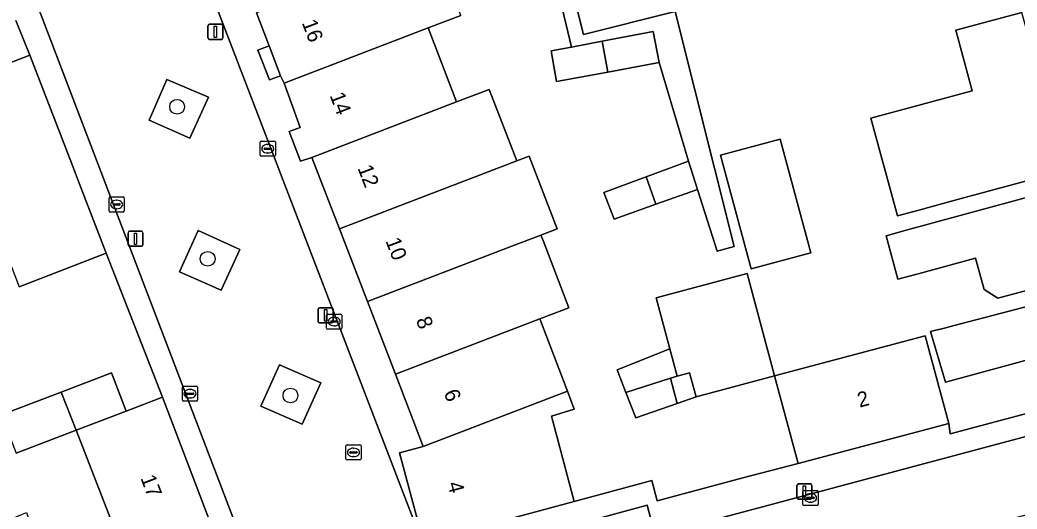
# Model space of a CAD drawing. Extents: x 159262 to 160143, y 383399 to 384319.
# Drawn here: x 159589.7 to 159655.5, y 383642.1 to 383674.4 of the extents above; entities that cross this region are included whole.
import ezdxf

# ---------------------------------------------------------------- set-up
doc = ezdxf.new("R2010")
doc.units = 0
for name, color, linetype in [('IMGEO_Boom', 7, 'Continuous'), ('IMGEO_Erf', 7, 'Continuous'), ('IMGEO_Groenvoorziening', 7, 'Continuous'), ('IMGEO_Hek', 7, 'Continuous'), ('IMGEO_Kolk', 7, 'Continuous'), ('IMGEO_Lichtmast', 7, 'Continuous'), ('IMGEO_Muur', 7, 'Continuous'), ('IMGEO_Pand', 7, 'Continuous'), ('IMGEO_Pand_nummerreeks', 7, 'Continuous'), ('IMGEO_Pand_overbouw', 7, 'Continuous'), ('IMGEO_Parkeervlak_open', 7, 'Continuous'), ('IMGEO_Rijbaan_lokaal_open', 7, 'Continuous'), ('IMGEO_Rioolput', 7, 'Continuous'), ('IMGEO_Voetpad_open', 7, 'Continuous')]:
    doc.layers.add(name, color=color, linetype=linetype)

msp = doc.modelspace()

# ---------------------------------------------------------------- linework, layer by layer
at = {"layer": 'IMGEO_Boom'}
for centre in [(159600.06, 383668.66), (159602.083, 383658.612), (159607.547, 383649.577)]:
    msp.add_circle(centre, 0.489, dxfattribs=at)
at = {"layer": 'IMGEO_Erf'}
for points in [[(159623.97, 383685.078), (159626.897, 383673.438), (159632.943, 383674.959), (159636.849, 383659.425), (159635.725, 383659.121), (159634.434, 383663.202), (159631.679, 383662.222), (159628.924, 383661.241), (159628.242, 383662.985), (159631.042, 383664.028), (159633.843, 383665.07), (159631.887, 383671.579), (159628.507, 383670.955), (159625.126, 383670.331), (159624.753, 383672.355), (159626.096, 383672.609), (159624.084, 383681.116)], [(159618.792, 383674.698), (159616.644, 383673.873), (159618.515, 383668.985), (159620.674, 383669.814), (159622.496, 383665.086), (159623.314, 383665.4), (159625.156, 383660.591), (159624.086, 383660.18), (159624.226, 383659.814), (159625.927, 383655.371), (159624.01, 383654.635), (159625.837, 383649.864), (159626.292, 383648.676), (159624.78, 383648.209), (159626.292, 383642.574), (159631.419, 383643.955), (159631.774, 383642.614), (159637.425, 383644.126), (159641.074, 383645.085), (159639.518, 383650.871), (159649.459, 383653.522), (159651.016, 383647.728), (159651.108, 383647.049), (159659.22, 383649.202)], [(159658.698, 383664.453), (159651.845, 383662.591), (159649.042, 383661.829), (159647.632, 383661.446), (159645.877, 383667.903), (159652.559, 383669.711), (159651.485, 383673.719), (159655.851, 383674.889)], [(159587.478, 383670.969), (159590.343, 383672.068), (159589.409, 383674.359)], [(159656.899, 383656.72), (159654.264, 383656.004), (159653.354, 383656.585), (159652.792, 383658.652), (159648.995, 383657.62), (159647.664, 383657.258), (159646.882, 383660.14), (159648.213, 383660.502), (159655.345, 383662.44), (159658.977, 383663.427)], [(159588.464, 383648.295), (159592.408, 383649.797), (159595.736, 383651.065), (159596.696, 383648.546), (159599.106, 383649.464), (159595.372, 383658.975), (159589.631, 383656.769)], [(159658.329, 383652.508), (159652.342, 383650.882), (159651.146, 383650.557), (159650.797, 383650.462), (159649.823, 383653.797), (159650.173, 383653.888), (159650.64, 383654.01), (159651.373, 383654.201), (159657.446, 383655.786)], [(159588.581, 383641.206), (159590.125, 383641.835), (159591.119, 383638.714), (159596.105, 383640.302), (159593.386, 383647.285), (159589.424, 383645.776)]]:
    msp.add_lwpolyline(points, dxfattribs=at)
for points in [[(159639.884, 383666.526), (159641.913, 383659.014), (159637.98, 383657.951), (159635.951, 383665.464)], [(159639.518, 383650.871), (159634.331, 383649.487), (159633.082, 383649.053), (159630.344, 383648.101), (159629.703, 383649.773), (159629.128, 383651.276), (159632.598, 383652.671), (159631.702, 383656.03), (159637.714, 383657.634)]]:
    msp.add_lwpolyline(points, close=True, dxfattribs=at)
at = {"layer": 'IMGEO_Groenvoorziening'}
for points in [[(159600.904, 383666.584), (159602.138, 383669.297), (159599.377, 383670.47), (159598.214, 383667.773)], [(159602.97, 383656.544), (159604.194, 383659.235), (159601.453, 383660.478), (159600.227, 383657.755)], [(159608.329, 383647.691), (159609.547, 383650.425), (159606.824, 383651.602), (159605.592, 383648.88)]]:
    msp.add_lwpolyline(points, close=True, dxfattribs=at)
at = {"layer": 'IMGEO_Hek'}
msp.add_lwpolyline([(159631.774, 383642.614), (159637.425, 383644.126)], dxfattribs=at)
at = {"layer": 'IMGEO_Kolk'}
for p, q in [((159605.547, 383665.465), (159605.547, 383666.317)), ((159605.622, 383666.391), (159606.474, 383666.391)), ((159605.849, 383665.934), (159606.247, 383665.934)), ((159606.035, 383666.171), (159606.06, 383666.171)), ((159606.548, 383666.317), (159606.548, 383665.465)), ((159606.474, 383665.391), (159605.622, 383665.391)), ((159605.806, 383665.885), (159605.806, 383665.897)), ((159606.244, 383665.848), (159605.846, 383665.848)), ((159606.058, 383665.611), (159606.033, 383665.611)), ((159606.29, 383665.897), (159606.29, 383665.885)), ((159595.566, 383661.779), (159595.566, 383662.631)), ((159595.641, 383662.705), (159596.493, 383662.705)), ((159596.567, 383662.631), (159596.567, 383661.779)), ((159595.825, 383662.199), (159595.825, 383662.211)), ((159596.263, 383662.162), (159595.865, 383662.162)), ((159595.868, 383662.248), (159596.266, 383662.248)), ((159596.054, 383662.485), (159596.079, 383662.485)), ((159596.309, 383662.211), (159596.309, 383662.199)), ((159596.493, 383661.705), (159595.641, 383661.705)), ((159596.077, 383661.925), (159596.052, 383661.925)), ((159609.935, 383654.037), (159609.935, 383654.889)), ((159610.01, 383654.963), (159610.862, 383654.963)), ((159610.423, 383654.743), (159610.448, 383654.743)), ((159610.936, 383654.889), (159610.936, 383654.037)), ((159610.194, 383654.457), (159610.194, 383654.469)), ((159610.632, 383654.42), (159610.234, 383654.42)), ((159610.237, 383654.506), (159610.635, 383654.506)), ((159610.446, 383654.183), (159610.421, 383654.183)), ((159610.678, 383654.469), (159610.678, 383654.457)), ((159610.862, 383653.963), (159610.01, 383653.963)), ((159600.415, 383649.268), (159600.415, 383650.12)), ((159600.49, 383650.194), (159601.342, 383650.194)), ((159601.416, 383650.12), (159601.416, 383649.268)), ((159600.674, 383649.688), (159600.674, 383649.7)), ((159601.112, 383649.651), (159600.714, 383649.651)), ((159600.717, 383649.737), (159601.115, 383649.737)), ((159600.903, 383649.974), (159600.928, 383649.974)), ((159601.158, 383649.7), (159601.158, 383649.688)), ((159601.342, 383649.194), (159600.49, 383649.194)), ((159600.926, 383649.414), (159600.901, 383649.414)), ((159641.392, 383642.378), (159641.392, 383643.23)), ((159641.467, 383643.304), (159642.319, 383643.304)), ((159641.88, 383643.084), (159641.905, 383643.084)), ((159642.393, 383643.23), (159642.393, 383642.378)), ((159642.319, 383642.304), (159641.467, 383642.304)), ((159641.651, 383642.798), (159641.651, 383642.81)), ((159642.089, 383642.761), (159641.691, 383642.761)), ((159641.694, 383642.847), (159642.092, 383642.847)), ((159641.903, 383642.524), (159641.878, 383642.524)), ((159642.135, 383642.81), (159642.135, 383642.798))]:
    msp.add_line(p, q, dxfattribs=at)
for points in [[(159605.547, 383665.465), (159605.547, 383666.317)], [(159605.622, 383666.391), (159606.474, 383666.391)], [(159606.548, 383666.317), (159606.548, 383665.465)], [(159606.474, 383665.391), (159605.622, 383665.391)], [(159595.566, 383661.779), (159595.566, 383662.631)], [(159595.641, 383662.705), (159596.493, 383662.705)], [(159596.567, 383662.631), (159596.567, 383661.779)], [(159596.493, 383661.705), (159595.641, 383661.705)], [(159609.935, 383654.037), (159609.935, 383654.889)], [(159610.01, 383654.963), (159610.862, 383654.963)], [(159610.936, 383654.889), (159610.936, 383654.037)], [(159610.862, 383653.963), (159610.01, 383653.963)], [(159600.415, 383649.268), (159600.415, 383650.12)], [(159600.49, 383650.194), (159601.342, 383650.194)], [(159601.416, 383650.12), (159601.416, 383649.268)], [(159601.342, 383649.194), (159600.49, 383649.194)], [(159641.392, 383642.378), (159641.392, 383643.23)], [(159641.467, 383643.304), (159642.319, 383643.304)], [(159642.393, 383643.23), (159642.393, 383642.378)], [(159642.319, 383642.304), (159641.467, 383642.304)]]:
    msp.add_lwpolyline(points, dxfattribs=at)
for centre, radius, start, end in [((159605.624, 383666.315), 0.0765, 91.55205, 178.44795), ((159605.624, 383666.315), 0.0765, 91.55205, 178.44795), ((159605.846, 383665.894), 0.0403, 85.87752, 175.75265), ((159606.251, 383665.896), 0.0386, 1.73085, 96.63898), ((159606.472, 383666.315), 0.0765, 1.55205, 88.44795), ((159606.472, 383666.315), 0.0765, 1.55205, 88.44795), ((159605.624, 383665.467), 0.0765, 181.55205, 268.44795), ((159605.624, 383665.467), 0.0765, 181.55205, 268.44795), ((159605.843, 383665.884), 0.0366, 178.93798, 274.71019), ((159606.247, 383665.891), 0.043, 264.86636, 352.45326), ((159606.472, 383665.467), 0.0765, 271.55205, 358.44795), ((159606.472, 383665.467), 0.0765, 271.55205, 358.44795), ((159595.643, 383662.629), 0.0765, 91.55205, 178.44795), ((159595.643, 383662.629), 0.0765, 91.55205, 178.44795), ((159596.491, 383662.629), 0.0765, 1.55205, 88.44795), ((159596.491, 383662.629), 0.0765, 1.55205, 88.44795), ((159595.865, 383662.208), 0.0403, 85.87752, 175.75265), ((159595.862, 383662.198), 0.0366, 178.93798, 274.71019), ((159596.266, 383662.205), 0.043, 264.86636, 352.45326), ((159596.27, 383662.21), 0.0386, 1.73085, 96.63898), ((159595.643, 383661.781), 0.0765, 181.55205, 268.44795), ((159595.643, 383661.781), 0.0765, 181.55205, 268.44795), ((159596.491, 383661.781), 0.0765, 271.55205, 358.44795), ((159596.491, 383661.781), 0.0765, 271.55205, 358.44795), ((159610.012, 383654.887), 0.0765, 91.55205, 178.44795), ((159610.012, 383654.887), 0.0765, 91.55205, 178.44795), ((159610.86, 383654.887), 0.0765, 1.55205, 88.44795), ((159610.86, 383654.887), 0.0765, 1.55205, 88.44795), ((159610.234, 383654.466), 0.0403, 85.87752, 175.75265), ((159610.231, 383654.456), 0.0366, 178.93798, 274.71019), ((159610.635, 383654.463), 0.043, 264.86636, 352.45326), ((159610.639, 383654.468), 0.0386, 1.73085, 96.63898), ((159610.012, 383654.039), 0.0765, 181.55205, 268.44795), ((159610.012, 383654.039), 0.0765, 181.55205, 268.44795), ((159610.86, 383654.039), 0.0765, 271.55205, 358.44795), ((159610.86, 383654.039), 0.0765, 271.55205, 358.44795), ((159600.492, 383650.118), 0.0765, 91.55205, 178.44795), ((159600.492, 383650.118), 0.0765, 91.55205, 178.44795), ((159601.34, 383650.118), 0.0765, 1.55205, 88.44795), ((159601.34, 383650.118), 0.0765, 1.55205, 88.44795), ((159600.714, 383649.697), 0.0403, 85.87752, 175.75265), ((159600.711, 383649.687), 0.0366, 178.93798, 274.71019), ((159601.115, 383649.694), 0.043, 264.86636, 352.45326), ((159601.119, 383649.699), 0.0386, 1.73085, 96.63898), ((159600.492, 383649.27), 0.0765, 181.55205, 268.44795), ((159600.492, 383649.27), 0.0765, 181.55205, 268.44795), ((159601.34, 383649.27), 0.0765, 271.55205, 358.44795), ((159601.34, 383649.27), 0.0765, 271.55205, 358.44795), ((159641.469, 383643.228), 0.0765, 91.55205, 178.44795), ((159641.469, 383643.228), 0.0765, 91.55205, 178.44795), ((159642.317, 383643.228), 0.0765, 1.55205, 88.44795), ((159642.317, 383643.228), 0.0765, 1.55205, 88.44795), ((159641.469, 383642.38), 0.0765, 181.55205, 268.44795), ((159641.469, 383642.38), 0.0765, 181.55205, 268.44795), ((159641.691, 383642.807), 0.0403, 85.87752, 175.75265), ((159641.688, 383642.797), 0.0366, 178.93798, 274.71019), ((159642.092, 383642.804), 0.043, 264.86636, 352.45326), ((159642.096, 383642.809), 0.0386, 1.73085, 96.63898), ((159642.317, 383642.38), 0.0765, 271.55205, 358.44795), ((159642.317, 383642.38), 0.0765, 271.55205, 358.44795)]:
    msp.add_arc(centre, radius, start, end, dxfattribs=at)
for centre, major_axis, ratio, start_param, end_param in [((159606.034, 383665.891), (-0.387, 0.002), 0.722429, 4.712389, 7.853982), ((159606.059, 383665.891), (-0.39, 0.002), 0.717154, 1.570796, 4.712389), ((159596.053, 383662.205), (-0.387, 0.002), 0.722429, 4.712389, 7.853982), ((159596.078, 383662.205), (-0.39, 0.002), 0.717154, 1.570796, 4.712389), ((159610.422, 383654.463), (-0.387, 0.002), 0.722429, 4.712389, 7.853982), ((159610.447, 383654.463), (-0.39, 0.002), 0.717154, 1.570796, 4.712389), ((159600.902, 383649.694), (-0.387, 0.002), 0.722429, 4.712389, 7.853982), ((159600.927, 383649.694), (-0.39, 0.002), 0.717154, 1.570796, 4.712389), ((159641.879, 383642.804), (-0.387, 0.002), 0.722429, 4.712389, 7.853982), ((159641.904, 383642.804), (-0.39, 0.002), 0.717154, 1.570796, 4.712389)]:
    msp.add_ellipse(centre, major_axis=major_axis, ratio=ratio, start_param=start_param, end_param=end_param, dxfattribs=at)
at = {"layer": 'IMGEO_Lichtmast'}
for p, q in [((159602.096, 383673.214), (159602.096, 383674.014)), ((159602.096, 383674.014), (159602.096, 383673.214)), ((159602.196, 383674.114), (159602.986, 383674.114)), ((159602.986, 383674.114), (159602.196, 383674.114)), ((159603.086, 383674.014), (159603.086, 383673.214)), ((159603.086, 383673.214), (159603.086, 383674.014)), ((159602.986, 383673.114), (159602.196, 383673.114)), ((159602.196, 383673.114), (159602.986, 383673.114)), ((159596.818, 383659.54), (159596.818, 383660.34)), ((159596.818, 383660.34), (159596.818, 383659.54)), ((159596.918, 383660.44), (159597.708, 383660.44)), ((159597.708, 383660.44), (159596.918, 383660.44)), ((159597.808, 383660.34), (159597.808, 383659.54)), ((159597.808, 383659.54), (159597.808, 383660.34)), ((159597.708, 383659.44), (159596.918, 383659.44)), ((159596.918, 383659.44), (159597.708, 383659.44)), ((159609.474, 383655.376), (159610.264, 383655.376)), ((159610.264, 383655.376), (159609.474, 383655.376)), ((159609.374, 383654.476), (159609.374, 383655.276)), ((159609.374, 383655.276), (159609.374, 383654.476)), ((159610.364, 383655.276), (159610.364, 383654.476)), ((159610.364, 383654.476), (159610.364, 383655.276)), ((159610.264, 383654.376), (159609.474, 383654.376)), ((159609.474, 383654.376), (159610.264, 383654.376)), ((159640.994, 383642.831), (159640.994, 383643.631)), ((159640.994, 383643.631), (159640.994, 383642.831)), ((159641.094, 383643.731), (159641.884, 383643.731)), ((159641.884, 383643.731), (159641.094, 383643.731)), ((159641.984, 383643.631), (159641.984, 383642.831)), ((159641.984, 383642.831), (159641.984, 383643.631)), ((159641.884, 383642.731), (159641.094, 383642.731)), ((159641.094, 383642.731), (159641.884, 383642.731))]:
    msp.add_line(p, q, dxfattribs=at)
for points in [[(159602.516, 383673.989), (159602.666, 383673.989), (159602.666, 383673.239), (159602.516, 383673.239), (159602.516, 383673.989)], [(159597.238, 383660.315), (159597.388, 383660.315), (159597.388, 383659.565), (159597.238, 383659.565), (159597.238, 383660.315)], [(159609.794, 383655.251), (159609.944, 383655.251), (159609.944, 383654.501), (159609.794, 383654.501), (159609.794, 383655.251)], [(159641.414, 383643.606), (159641.564, 383643.606), (159641.564, 383642.856), (159641.414, 383642.856), (159641.414, 383643.606)]]:
    msp.add_lwpolyline(points, dxfattribs=at)
for centre, start, end in [((159602.196, 383674.014), 90, 180), ((159602.196, 383674.014), 90, 180), ((159602.986, 383674.014), 0, 90), ((159602.986, 383674.014), 360, 90), ((159602.196, 383673.214), 180, 270), ((159602.196, 383673.214), 180, 270), ((159602.986, 383673.214), 270, 0), ((159602.986, 383673.214), 270, 0), ((159596.918, 383660.34), 90, 180), ((159596.918, 383660.34), 90, 180), ((159597.708, 383660.34), 0, 90), ((159597.708, 383660.34), 360, 90), ((159596.918, 383659.54), 180, 270), ((159596.918, 383659.54), 180, 270), ((159597.708, 383659.54), 270, 0), ((159597.708, 383659.54), 270, 0), ((159609.474, 383655.276), 90, 180), ((159609.474, 383655.276), 90, 180), ((159610.264, 383655.276), 0, 90), ((159610.264, 383655.276), 360, 90), ((159609.474, 383654.476), 180, 270), ((159609.474, 383654.476), 180, 270), ((159610.264, 383654.476), 270, 0), ((159610.264, 383654.476), 270, 0), ((159641.094, 383643.631), 90, 180), ((159641.094, 383643.631), 90, 180), ((159641.884, 383643.631), 0, 90), ((159641.884, 383643.631), 360, 90), ((159641.094, 383642.831), 180, 270), ((159641.094, 383642.831), 180, 270), ((159641.884, 383642.831), 270, 0), ((159641.884, 383642.831), 270, 0)]:
    msp.add_arc(centre, 0.1, start, end, dxfattribs=at)
at = {"layer": 'IMGEO_Muur'}
for points in [[(159595.372, 383658.975), (159599.106, 383649.464)], [(159651.016, 383647.728), (159651.108, 383647.049), (159659.22, 383649.202)], [(159637.425, 383644.126), (159641.074, 383645.085)], [(159626.292, 383642.574), (159631.419, 383643.955), (159631.774, 383642.614)]]:
    msp.add_lwpolyline(points, dxfattribs=at)
at = {"layer": 'IMGEO_Pand'}
for points in [[(159605.294, 383674.866), (159606.147, 383672.702), (159606.896, 383670.715), (159607.13, 383670.22), (159616.644, 383673.873), (159618.792, 383674.698), (159616.995, 383679.359)], [(159661.769, 383672.22), (159661.027, 383672.019), (159656.944, 383670.909), (159655.851, 383674.889), (159651.485, 383673.719), (159652.559, 383669.711), (159645.877, 383667.903), (159647.632, 383661.446), (159649.042, 383661.829), (159651.845, 383662.591), (159658.698, 383664.453), (159663.523, 383665.764)], [(159616.644, 383673.873), (159607.13, 383670.22), (159608.189, 383667.299), (159607.453, 383667.031), (159608.202, 383665.057), (159608.961, 383665.317), (159618.515, 383668.985)], [(159628.507, 383670.955), (159631.887, 383671.579), (159631.508, 383673.631), (159628.13, 383672.993)], [(159628.13, 383672.993), (159626.096, 383672.609), (159624.753, 383672.355), (159625.126, 383670.331), (159628.507, 383670.955)], [(159588.522, 383659.657), (159589.631, 383656.769), (159595.372, 383658.975), (159593.814, 383663.032), (159593.104, 383664.88), (159590.343, 383672.068), (159587.478, 383670.969), (159587.185, 383671.713), (159585.329, 383671.001), (159585.601, 383670.247), (159584.982, 383670.008), (159589.017, 383659.853)], [(159610.782, 383660.589), (159620.327, 383664.254), (159622.496, 383665.086), (159620.674, 383669.814), (159618.515, 383668.985), (159608.961, 383665.317)], [(159639.884, 383666.526), (159635.951, 383665.464), (159637.98, 383657.951), (159641.913, 383659.014)], [(159624.086, 383660.18), (159625.156, 383660.591), (159623.314, 383665.4), (159622.496, 383665.086), (159620.327, 383664.254), (159610.782, 383660.589), (159612.634, 383655.783), (159622.169, 383659.444)], [(159631.042, 383664.028), (159631.679, 383662.222), (159634.434, 383663.202), (159633.843, 383665.07)], [(159663.802, 383664.738), (159658.977, 383663.427), (159655.345, 383662.44), (159648.213, 383660.502), (159646.882, 383660.14), (159647.664, 383657.258), (159648.995, 383657.62), (159652.792, 383658.652), (159653.354, 383656.585), (159654.264, 383656.004), (159656.899, 383656.72), (159660.531, 383657.707), (159665.356, 383659.017)], [(159631.042, 383664.028), (159628.242, 383662.985), (159628.924, 383661.241), (159631.679, 383662.222)], [(159624.086, 383660.18), (159622.169, 383659.444), (159612.634, 383655.783), (159614.485, 383650.978), (159624.01, 383654.635), (159625.927, 383655.371), (159624.226, 383659.814)], [(159665.632, 383658.01), (159660.807, 383656.699), (159657.446, 383655.786), (159651.373, 383654.201), (159650.64, 383654.01), (159650.173, 383653.888), (159649.823, 383653.797), (159650.797, 383650.462), (159651.146, 383650.557), (159652.342, 383650.882), (159658.329, 383652.508), (159659.22, 383649.202), (159662.598, 383650.107), (159667.423, 383651.418), (159667.279, 383651.948)], [(159637.714, 383657.634), (159631.702, 383656.03), (159632.598, 383652.671), (159633.081, 383650.858), (159633.906, 383651.078), (159634.331, 383649.487), (159639.518, 383650.871)], [(159624.01, 383654.635), (159614.485, 383650.978), (159616.321, 383646.21), (159625.837, 383649.864)], [(159649.459, 383653.522), (159639.518, 383650.871), (159641.074, 383645.085), (159651.016, 383647.728)], [(159632.598, 383652.671), (159629.128, 383651.276), (159629.703, 383649.773), (159632.639, 383650.716), (159633.081, 383650.858)], [(159592.408, 383649.797), (159593.386, 383647.285), (159596.696, 383648.546), (159595.736, 383651.065)], [(159633.906, 383651.078), (159633.081, 383650.858), (159632.639, 383650.716), (159633.082, 383649.053), (159634.331, 383649.487)], [(159632.639, 383650.716), (159629.703, 383649.773), (159630.344, 383648.101), (159633.082, 383649.053)], [(159592.408, 383649.797), (159588.464, 383648.295), (159589.424, 383645.776), (159593.386, 383647.285)], [(159599.106, 383649.464), (159596.696, 383648.546), (159593.386, 383647.285), (159596.105, 383640.302), (159597.123, 383637.687), (159602.802, 383639.758)], [(159624.78, 383648.209), (159626.292, 383648.676), (159625.837, 383649.864), (159616.321, 383646.21), (159614.756, 383645.792), (159616.332, 383639.888), (159619.646, 383640.782), (159626.292, 383642.574)]]:
    msp.add_lwpolyline(points, close=True, dxfattribs=at)
at = {"layer": 'IMGEO_Pand_overbouw'}
msp.add_lwpolyline([(159606.896, 383670.715), (159606.147, 383672.702), (159605.381, 383672.413), (159606.152, 383670.433)], close=True, dxfattribs=at)
at = {"layer": 'IMGEO_Parkeervlak_open'}
msp.add_lwpolyline([(159620.533, 383637.313), (159631.622, 383640.314), (159631.103, 383642.326), (159620.021, 383639.316)], close=True, dxfattribs=at)
at = {"layer": 'IMGEO_Rijbaan_lokaal_open'}
msp.add_lwpolyline([(159620.533, 383637.313), (159621.563, 383632.459), (159669.137, 383645.181), (159669.235, 383645.207), (159667.9, 383650.013), (159667.815, 383649.99), (159631.622, 383640.314)], close=True, dxfattribs=at)
at = {"layer": 'IMGEO_Rioolput'}
for p, q in [((159611.21, 383645.389), (159611.21, 383646.241)), ((159611.285, 383646.315), (159612.137, 383646.315)), ((159612.211, 383646.241), (159612.211, 383645.389)), ((159611.469, 383645.809), (159611.469, 383645.821)), ((159611.907, 383645.772), (159611.509, 383645.772)), ((159611.512, 383645.858), (159611.91, 383645.858)), ((159611.721, 383645.535), (159611.696, 383645.535)), ((159611.698, 383646.095), (159611.723, 383646.095)), ((159611.953, 383645.821), (159611.953, 383645.809)), ((159612.137, 383645.315), (159611.285, 383645.315))]:
    msp.add_line(p, q, dxfattribs=at)
for points in [[(159611.21, 383645.389), (159611.21, 383646.241)], [(159611.285, 383646.315), (159612.137, 383646.315)], [(159612.211, 383646.241), (159612.211, 383645.389)], [(159612.137, 383645.315), (159611.285, 383645.315)]]:
    msp.add_lwpolyline(points, dxfattribs=at)
for centre, radius, start, end in [((159611.287, 383646.239), 0.0765, 91.55205, 178.44795), ((159611.287, 383646.239), 0.0765, 91.55205, 178.44795), ((159612.135, 383646.239), 0.0765, 1.55205, 88.44795), ((159612.135, 383646.239), 0.0765, 1.55205, 88.44795), ((159611.509, 383645.818), 0.0403, 85.87752, 175.75265), ((159611.506, 383645.808), 0.0366, 178.93798, 274.71019), ((159611.91, 383645.815), 0.043, 264.86636, 352.45326), ((159611.914, 383645.82), 0.0386, 1.73085, 96.63898), ((159611.287, 383645.391), 0.0765, 181.55205, 268.44795), ((159611.287, 383645.391), 0.0765, 181.55205, 268.44795), ((159612.135, 383645.391), 0.0765, 271.55205, 358.44795), ((159612.135, 383645.391), 0.0765, 271.55205, 358.44795)]:
    msp.add_arc(centre, radius, start, end, dxfattribs=at)
for centre, major_axis, ratio, start_param, end_param in [((159611.697, 383645.815), (-0.387, 0.002), 0.722429, 4.712389, 7.853982), ((159611.722, 383645.815), (-0.39, 0.002), 0.717154, 1.570796, 4.712389)]:
    msp.add_ellipse(centre, major_axis=major_axis, ratio=ratio, start_param=start_param, end_param=end_param, dxfattribs=at)
at = {"layer": 'IMGEO_Voetpad_open'}
for points in [[(159619.379, 383631.734), (159597.575, 383688.534), (159587.311, 383684.551), (159609.011, 383627.739)], [(159609.011, 383627.739), (159587.311, 383684.551), (159597.575, 383688.534), (159619.379, 383631.734)], [(159606.896, 383670.715), (159606.147, 383672.702), (159605.381, 383672.413), (159606.152, 383670.433)], [(159600.904, 383666.584), (159598.214, 383667.773), (159599.377, 383670.47), (159602.138, 383669.297)], [(159602.97, 383656.544), (159600.227, 383657.755), (159601.453, 383660.478), (159604.194, 383659.235)], [(159608.329, 383647.691), (159605.592, 383648.88), (159606.824, 383651.602), (159609.547, 383650.425)], [(159667.815, 383649.99), (159667.423, 383651.418), (159662.598, 383650.107), (159659.22, 383649.202), (159651.108, 383647.049), (159651.016, 383647.728), (159641.074, 383645.085), (159637.425, 383644.126), (159631.774, 383642.614), (159631.419, 383643.955), (159626.292, 383642.574), (159619.646, 383640.782), (159620.021, 383639.316), (159631.103, 383642.326), (159631.622, 383640.314)]]:
    msp.add_lwpolyline(points, close=True, dxfattribs=at)
for points in [[(159624.084, 383681.116), (159626.096, 383672.609), (159628.13, 383672.993), (159631.508, 383673.631), (159631.887, 383671.579), (159633.843, 383665.07), (159634.434, 383663.202), (159635.725, 383659.121), (159636.849, 383659.425), (159632.943, 383674.959), (159626.897, 383673.438), (159623.97, 383685.078)], [(159616.332, 383639.888), (159614.756, 383645.792), (159616.321, 383646.21), (159614.485, 383650.978), (159612.634, 383655.783), (159610.782, 383660.589), (159608.961, 383665.317), (159608.202, 383665.057), (159607.453, 383667.031), (159608.189, 383667.299), (159607.13, 383670.22), (159606.896, 383670.715), (159606.152, 383670.433), (159605.381, 383672.413), (159606.147, 383672.702), (159605.294, 383674.866)], [(159589.409, 383674.359), (159590.343, 383672.068), (159593.104, 383664.88), (159593.814, 383663.032), (159595.372, 383658.975), (159599.106, 383649.464), (159602.802, 383639.758)]]:
    msp.add_lwpolyline(points, dxfattribs=at)

# ---------------------------------------------------------------- texts
at = {"layer": 'IMGEO_Pand_nummerreeks'}
for s, rotation, p in [('16', 290.97165, (159608.283, 383674.221)), ('14', 290.97165, (159610.125, 383669.416)), ('12', 290.97165, (159611.964, 383664.618)), ('10', 290.97004, (159613.809, 383659.804)), ('8', 290.97004, (159615.816, 383654.57)), ('6', 290.97165, (159617.656, 383649.768)), ('2', 14.88951, (159645.129, 383648.771)), ('17', 290.84399, (159597.628, 383644.128)), ('4', 284.94826, (159617.909, 383643.753))]:
    msp.add_text(s, height=1, rotation=rotation, dxfattribs=at).set_placement(p)

doc.saveas('drawing.dxf')
